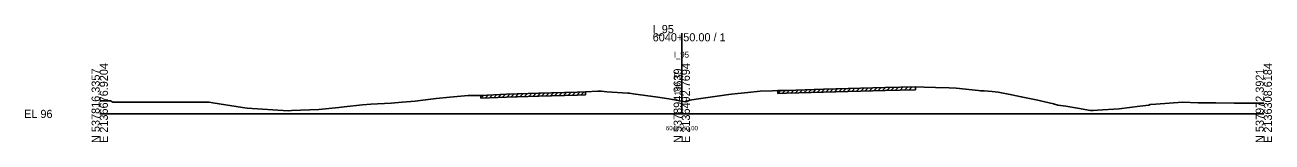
# Model space of a CAD drawing. Extents: x -12534 to 3403, y -1332 to 21983.
# Drawn here: x 1974.3 to 2402.8, y 5490.3 to 5530.6 of the extents above; entities that cross this region are included whole.
import ezdxf

# ---------------------------------------------------------------- set-up
doc = ezdxf.new("R2010")
doc.units = 0
for name, color, linetype in [('RD_GPK_XS_Cell', 7, 'Continuous'), ('RD_XS_ExGround', 7, 'Continuous'), ('RD_XS_ExPaveRet', 7, 'Continuous'), ('RD_XS_TX_Baseline', 7, 'Continuous'), ('RD_XS_TX_Elev_EX', 7, 'Continuous'), ('RD_XS_TX_Station', 7, 'Continuous')]:
    doc.layers.add(name, color=color, linetype=linetype)

msp = doc.modelspace()

# ---------------------------------------------------------------- linework, layer by layer
at = {"layer": 'RD_GPK_XS_Cell'}
for p, q in [((2200, 5500), (2200, 5527.75)), ((2000, 5500), (2200, 5500)), ((2200, 5500), (2400, 5500))]:
    msp.add_line(p, q, dxfattribs=at)
at = {"layer": 'RD_XS_ExGround'}
msp.add_lwpolyline([(2000, 5504.47), (2003.67, 5504.49), (2004.55, 5504.08), (2014.61, 5504.02), (2016.07, 5504.05), (2036.9, 5504.05), (2037.66, 5504.04), (2038.9, 5503.85), (2049.04, 5502.16), (2050.64, 5502.01), (2064.77, 5501.1), (2065.95, 5501.18), (2075.25, 5501.49), (2082.14, 5502.25), (2084.04, 5502.46), (2090.3, 5503.1), (2093.18, 5503.29), (2100.15, 5503.69), (2103.97, 5504.06), (2108.34, 5504.34), (2111.93, 5504.81), (2115.58, 5505.25), (2120.32, 5505.78), (2122.82, 5506.02), (2126.66, 5506.31), (2127.81, 5506.36), (2130.92, 5506.35), (2139.82, 5506.78), (2150.93, 5507.15), (2164.06, 5507.49), (2166.89, 5507.57), (2171.13, 5507.76), (2171.49, 5507.79), (2172.44, 5507.79), (2174.31, 5507.64), (2181.44, 5507.14), (2182.02, 5507.11), (2183.32, 5506.89), (2191.79, 5505.7), (2194.09, 5505.38), (2195.58, 5505.16), (2200, 5504.37), (2201.27, 5504.15), (2202.82, 5504.67), (2204.98, 5505.12), (2209.8, 5505.72), (2216.17, 5506.66), (2217.05, 5506.79), (2219.24, 5507.03), (2222.7, 5507.41), (2226.91, 5507.79), (2231.22, 5507.98), (2233, 5508.04), (2236.03, 5508.08), (2248.68, 5508.47), (2269.9, 5509.09), (2280.37, 5509.25), (2283.26, 5509.18), (2287.15, 5509.08), (2291.91, 5508.99), (2294.27, 5508.82), (2301.96, 5508.06), (2302.64, 5507.98), (2303.9, 5507.91), (2305.27, 5507.85), (2306.61, 5507.72), (2308.73, 5507.43), (2313.47, 5506.53), (2316.66, 5505.9), (2321.82, 5504.82), (2327.76, 5503.45), (2329.27, 5502.99), (2332, 5502.67), (2335.98, 5502.02), (2340.47, 5501.2), (2341.42, 5501.13), (2342.91, 5501.26), (2350.35, 5501.7), (2357.46, 5502.69), (2360.45, 5503.05), (2360.91, 5503.18), (2362.94, 5503.38), (2372.08, 5503.98), (2377.42, 5503.85), (2383.53, 5503.8), (2389.83, 5503.7), (2396.53, 5503.65), (2400, 5503.68)], dxfattribs=at)
at = {"layer": 'RD_XS_ExPaveRet'}
for p, q in [((2136.92, 5505.64), (2137.97, 5506.69)), ((2138.42, 5505.71), (2139.47, 5506.76)), ((2139.92, 5505.78), (2140.95, 5506.81)), ((2141.42, 5505.83), (2142.45, 5506.87)), ((2142.92, 5505.88), (2143.95, 5506.92)), ((2144.42, 5505.93), (2145.45, 5506.97)), ((2145.92, 5505.98), (2146.95, 5507.02)), ((2147.42, 5506.03), (2148.45, 5507.07)), ((2148.92, 5506.08), (2149.95, 5507.12)), ((2150.42, 5506.14), (2151.45, 5507.17)), ((2151.92, 5506.18), (2152.95, 5507.2)), ((2153.42, 5506.22), (2154.45, 5507.24)), ((2154.92, 5506.26), (2155.95, 5507.28)), ((2156.42, 5506.29), (2157.45, 5507.32)), ((2157.92, 5506.33), (2158.95, 5507.36)), ((2159.42, 5506.37), (2160.45, 5507.4)), ((2160.92, 5506.41), (2161.95, 5507.44)), ((2162.42, 5506.45), (2163.45, 5507.47)), ((2163.92, 5506.49), (2164.95, 5507.51)), ((2165.42, 5506.53), (2166.45, 5507.56)), ((2166.89, 5507.57), (2166.89, 5506.57)), ((2233, 5507.04), (2234.02, 5508.05)), ((2233, 5507.04), (2233, 5508.04)), ((2233, 5507.04), (2236.03, 5507.08)), ((2234.5, 5507.06), (2235.52, 5508.08)), ((2236, 5507.08), (2237.04, 5508.11)), ((2236.03, 5507.08), (2248.68, 5507.47)), ((2237.5, 5507.13), (2238.54, 5508.16)), ((2239, 5507.17), (2240.04, 5508.2)), ((2240.5, 5507.22), (2241.54, 5508.25)), ((2242, 5507.26), (2243.04, 5508.3)), ((2243.5, 5507.31), (2244.54, 5508.34)), ((2245, 5507.36), (2246.04, 5508.39)), ((2246.5, 5507.4), (2247.54, 5508.43)), ((2248, 5507.45), (2249.04, 5508.48)), ((2248.68, 5507.47), (2269.9, 5508.09)), ((2249.5, 5507.49), (2250.53, 5508.52)), ((2251, 5507.54), (2252.03, 5508.57)), ((2252.5, 5507.58), (2253.53, 5508.61)), ((2254, 5507.62), (2255.03, 5508.65)), ((2255.5, 5507.67), (2256.53, 5508.7)), ((2257, 5507.71), (2258.03, 5508.74)), ((2258.5, 5507.76), (2259.53, 5508.79)), ((2260, 5507.8), (2261.03, 5508.83)), ((2261.5, 5507.84), (2262.53, 5508.87)), ((2263, 5507.89), (2264.03, 5508.92)), ((2264.5, 5507.93), (2265.53, 5508.96)), ((2266, 5507.98), (2267.03, 5509.01)), ((2267.5, 5508.02), (2268.53, 5509.05)), ((2269, 5508.06), (2270.03, 5509.09)), ((2269.9, 5508.09), (2280.37, 5508.25)), ((2270.5, 5508.1), (2271.52, 5509.11)), ((2272, 5508.12), (2273.02, 5509.14)), ((2273.5, 5508.15), (2274.52, 5509.16)), ((2275, 5508.17), (2276.02, 5509.18)), ((2276.5, 5508.19), (2277.52, 5509.21)), ((2278, 5508.21), (2279.02, 5509.23)), ((2280.37, 5509.25), (2280.37, 5508.25)), ((2130.92, 5505.35), (2131.97, 5506.4)), ((2130.92, 5505.35), (2130.92, 5506.35)), ((2130.92, 5505.35), (2139.82, 5505.78)), ((2132.42, 5505.42), (2133.47, 5506.47)), ((2133.92, 5505.49), (2134.97, 5506.54)), ((2135.42, 5505.57), (2136.47, 5506.62)), ((2139.82, 5505.78), (2150.93, 5506.15)), ((2150.93, 5506.15), (2164.06, 5506.49)), ((2164.06, 5506.49), (2166.89, 5506.57))]:
    msp.add_line(p, q, dxfattribs=at)

# ---------------------------------------------------------------- texts
at = {"layer": 'RD_GPK_XS_Cell'}
for s, p in [('I_95', (2190, 5527.75)), ('6040+50.00 / 1', (2190, 5524.95)), ('EL 96', (1974, 5498.6))]:
    msp.add_text(s, height=2.8, dxfattribs=at).set_placement(p)
for s, p in [('N 537816.3357', (2000, 5490)), ('E 2136676.9204', (2002.8, 5490)), ('N 537894.3639', (2200, 5490)), ('E 2136492.7694', (2202.8, 5490)), ('N 537972.3921', (2400, 5490)), ('E 2136308.6184', (2402.8, 5490))]:
    msp.add_text(s, height=2.8, rotation=90, dxfattribs=at).set_placement(p)
at = {"layer": 'RD_XS_TX_Baseline'}
msp.add_text('I_95', height=2, dxfattribs=at).set_placement((2197.28, 5519.37))
at = {"layer": 'RD_XS_TX_Elev_EX'}
msp.add_text('100.37', height=2, rotation=90, dxfattribs=at).set_placement((2199.5, 5506.37))
at = {"layer": 'RD_XS_TX_Station'}
msp.add_text('6040+50.00', height=1.5, dxfattribs=at).set_placement((2194.56, 5494.37))

doc.saveas('drawing.dxf')
